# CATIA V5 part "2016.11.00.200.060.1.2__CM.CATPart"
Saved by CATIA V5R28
Part number: 2016.11.00.200.060.1.2__CM
Property "id_number": "2016.11.00.200.060.1.2"
Publications: "Absolute Axis System", "driver", "slider", "base", "cam diagram"
Bounding box of the stored display mesh (mm): x -60 to 220, y -155 to 155, z 0 to 300
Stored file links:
  N:\B2\Normteile\K\2016\11-14\020\cm\2016.11.00.200.060.1.2__CM.CATPart
  H:\CAD_Startmodelle\Tests\fill-in_PRT-SL_TEMPLATE.xlsx
  H:\CAD_Startmodelle\V5-R24\R24_TEMPLATE_PRT_FIBRO_CAM_TECNOLOGIES_INDEX.xlsx
  H:\z_Einordnen\170511__Anfrage_TK_HN\170511__CC01_TKHN.CATPart
  N:\B2\Normteile\K\2016\9xxx\2016.9024.1705.001\Entwurf_\170511__CC01_TKHN.CATPart
  N:\B2\Normteile\K\2016\9xxx\2016.9024.1707.006\Konstruktion\2016.9024.1707.006__HP__CUSTOMIZED_CAM_CM.CATPart
  N:\B2\Normteile\K\2016\9xxx\2016.9024.1707.005\Konstruktion\2016.9024.1707.005__HP__CUSTOMIZED_CAM_CM.CATPart
  N:\B2\Normteile\K\2016\9xxx\2016.9024.1707.008\Konstruktion\2016.9024.1707.008__HP__CUSTOMIZED_CAM_CM.CATPart
  N:\B2\Normteile\K\2016\9xxx\2016.9024.1707.009\Konstruktion\2016.9024.1707.009__HP__CUSTOMIZED_CAM_CM.CATPart
  N:\B2\Normteile\K\2016\9xxx\2016.9024.1707.010\Konstruktion\2016.9024.1707.010__HP__CUSTOMIZED_CAM_CM.CATPart
  N:\B2\Normteile\K\2016\9xxx\2016.9024.1708.002\Konstruktion\2016.9024.1708.002__HP__CUSTOMIZED_CAM_CM.CATPart
  N:\B2\Normteile\K\2016\9xxx\2016.9024.1802.001\Konstruktion\2016.9024.1802.001__HP__CUSTOMIZED_CAM_CM.CATPart
  N:\B2\Normteile\K\2016\9xxx\2016.9024.1802.002\Konstruktion\2016.9024.1802.002__HP__CUSTOMIZED_CAM_CM.CATPart
  N:\B2\Normteile\K\2016\9xxx\2016.9024.1811.003\Konstruktion\2016.9024.1811.003__HP__CUSTOMIZED_CAM_CM.CATPart
  N:\B2\Normteile\K\2016\9xxx\2016.9015.1811.001\Konstruktion\am\2016.9015.1811.001__AM__FCC_HV_DMC_0125-00.CATPart
  N:\B2\Normteile\K\2016\9xxx\2016.9024.1811.009\Konstruktion\2016.9024.1811.009__HP__CUSTOMIZED_CAM_CM.CATPart
  N:\B2\Normteile\K\2016\9xxx\2016.9024.1911.002\Konstruktion\am\2016.9024.1911.002__AM__CUSTOMIZED_CAM_CM.CATPart
  N:\B2\Normteile\K\2016\9xxx\2016.9024.2002.006\Konstruktion\2016.9024.2002.006__AM.CATPart
  N:\B2\Normteile\K\2016\9xxx\2016.9024.2004.001\Konstruktion\2016.9024.2004.001__AM__FCC_HV_CAEC_0260-45.CATPart
  N:\B2\Normteile\K\2016\9xxx\2016.9024.2006.002\Konstruktion\2016.9024.2006.002__AM__FCC_HV_CAEC_0260-40.CATPart
  N:\B2\Normteile\K\2016\9xxx\2016.9024.2006.005\Konstruktion\am\2016.9024.2006.005__AM__CFCC_HV_AEPC_0080-65.CATPart
  N:\B2\Normteile\K\2016\9xxx\2016.9024.2006.004\Konstruktion\am\2016.9024.2006.004__AM__CFCC_HV_AEC_0210-35.CATPart
  N:\B2\Normteile\K\2016\9xxx\2016.9026.2006.001\Konstruktion\am\2016.9026.2006.001__AM__FCC_LV_CAEC_0180-40.CATPart
  N:\B2\Normteile\K\2016\9xxx\2016.9015.2007.001\Konstruktion\am\2016.9015.2007.001__AM__FCC_HV_CDMPC_0090-00.CATPart
  N:\B2\Normteile\K\2016\9xxx\2016.9024.2005.001\Konstruktion\am\2016.9024.2005.001__AM__CFCC_HV_AEPC_1400-70.CATPart
  N:\B2\Normteile\K\2016\9xxx\2016.9024.2007.004\Konstruktion\am\2016.9024.2007.004__AM__CFCC_HV_AEC_1250-80.CATPart
  N:\B2\Normteile\K\2016\11-14\005\2016.11.00.052.040.1.02__AS__DIE_MOUNT_CAM__W52_A0_S40.CATProduct
  N:\B2\Normteile\K\2016\11-14\015\2016.11.00.150.060.1.02__AS__DIE_MOUNT_CAM__W150_A0_S60.CATProduct
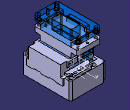
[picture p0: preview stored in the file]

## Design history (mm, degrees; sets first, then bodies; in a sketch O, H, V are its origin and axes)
Parameters
  group "process_parameters"
    modeltype = ""
    stocklist = ""
    id_number = "2016.11.00.200.060.1.2"
    id_number_rough_part = ""
    revision_index = ""
    revision_date = ""
    revision_description = ""
    category = ""
    material = ""
    manufacturing_information = ""
    standard = ""
  group "release_parameters_startmodel"
    sm_revision_index = "2016_00" {design table}
    sm_revision_date = "20.08.2016" {design table}
    sm_revision_name = "Meyer" {design table}
    sm_revision_description = "new part template FIBRO cam tecnologies" {design table}
AxisSystem1: origin (0, 0, 0), X (1, 0, 0), Y (0, 1, 0), Z (0, 0, 1)
Set1 "reference elements"
  Sketch1 "cam diagram" on ZX plane of AxisSystem1, origin (0, 0, 0), H (-1, 0, 0), V (0, 0, 1)
    line L1 (0, 0) -> (60, 0)
    line L2 (60, 0) -> (0, 60)
    point P2 (0, 60)
    line L3 (0, 60) -> (0, 0)
    length L1 = 60
    angle H L2 = 45
    horizontal: L1 H
    coincidence: P2 V
    vertical: L3 V
Body1 "finished_part" (main body)
  Body2 "rough_part"
  Add1 "rough_part": tool Body2
  Body3 "milling operations"
  Remove1 "milling operations": tool Body3
  Body4 "drilling operations"
  Remove2 "drilling operations": tool Body4
Body5 "driver"
  Solid1: solid without history
Body6 "slider"
  Solid2: solid without history
Body7 "base"
  Solid3: solid without history
Body8 "opened position"
  Body9 "slider"
    Body10 "slider"
      Solid4: linked copy from another document
    Assemble1: tool Body10
    Translate1: FirstPoint vertex [element of Sketch1 | element of Sketch1], SecondPoint vertex [element of Sketch1 | element of Sketch1], ToTransfor Assemble1
  Assemble2: tool Body9
  Body11 "driver"
    Body12 "driver"
      Solid5: linked copy from another document
    Assemble3: tool Body12
    Translate2: FirstPoint vertex [element of Sketch1 | element of Sketch1], SecondPoint vertex [element of Sketch1 | element of Sketch1], ToTransfor Assemble3
  Assemble4: tool Body11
